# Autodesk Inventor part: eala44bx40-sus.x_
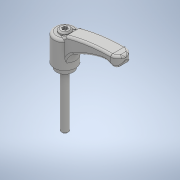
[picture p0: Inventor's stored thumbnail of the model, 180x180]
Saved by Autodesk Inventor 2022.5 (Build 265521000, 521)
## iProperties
Created: 2018-05
Part Number: eala44bx40-sus.x_
Material: 一般
Document SubType Name: Modeling
Designer: imaocorp
Density: 1 g/cm^3
Appearance: 既定
Sending System: SOLIDWORKS 2016-2016286
MC: AMD64
MC_MODEL: AMD64 Family 21 Model 2 Stepping 0, AuthenticAMD
OS: Windows_NT
FRU: Parasolid Version 28.0, build 224,  7-29-2016
FORMAT: text
GUISE: transmit
KEY: eala44bx40-sus
FILE: eala44bx40-sus.x_t
DATE: Fri May 18 11:28:31 2018
Author: imaocorp
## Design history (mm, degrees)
feature "Base1"
node "ソリッド1"
